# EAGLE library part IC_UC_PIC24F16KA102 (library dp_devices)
16-Bit Flash PIC Microcontroller Mfr no: PIC24F16KA102 PIC24F16KA102
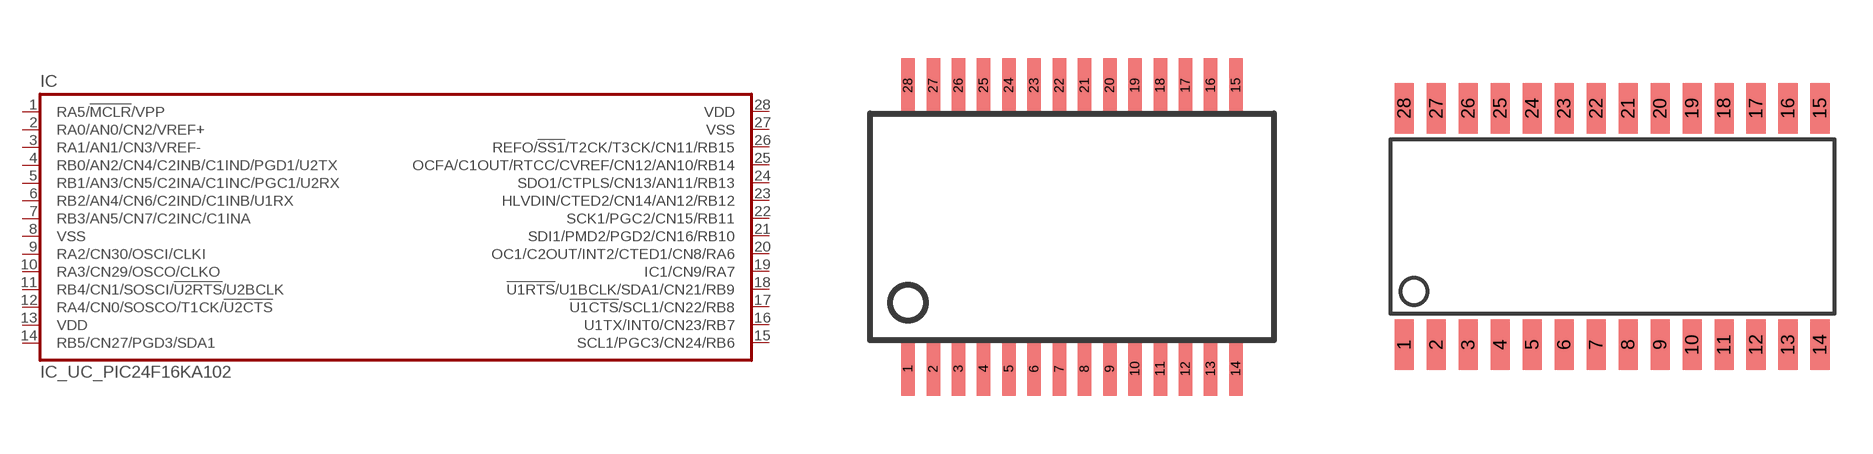
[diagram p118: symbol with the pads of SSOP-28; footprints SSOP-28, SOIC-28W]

Designator prefix IC

## IC_UC_PIC24F16KA102-SSOP  [SSOP-28]
1  RA5/!MCLR!/VPP  in
2  RA0/AN0/CN2/VREF+
3  RA1/AN1/CN3/VREF-
4  RB0/AN2/CN4/C2INB/C1IND/PGD1/U2TX
5  RB1/AN3/CN5/C2INA/C1INC/PGC1/U2RX
6  RB2/AN4/CN6/C2IND/C1INB/U1RX
7  RB3/AN5/CN7/C2INC/C1INA
8  VSS  sup
9  RA2/CN30/OSCI/CLKI
10  RA3/CN29/OSCO/CLKO
11  RB4/CN1/SOSCI/!U2RTS!/U2BCLK
12  RA4/CN0/SOSCO/T1CK/!U2CTS!
13  VDD  sup
14  RB5/CN27/PGD3/SDA1
15  SCL1/PGC3/CN24/RB6
16  U1TX/INT0/CN23/RB7
17  !U1CTS!/SCL1/CN22/RB8
18  !U1RTS!/U1BCLK/SDA1/CN21/RB9
19  IC1/CN9/RA7  pwr
20  OC1/C2OUT/INT2/CTED1/CN8/RA6  pwr
21  SDI1/PMD2/PGD2/CN16/RB10
22  SCK1/PGC2/CN15/RB11
23  HLVDIN/CTED2/CN14/AN12/RB12
24  SDO1/CTPLS/CN13/AN11/RB13
25  OCFA/C1OUT/RTCC/CVREF/CN12/AN10/RB14
26  REFO/!SS1!/T2CK/T3CK/CN11/RB15
27  VSS  sup
28  VDD  sup

## IC_UC_PIC24F16KA102-SOIC  [SOIC-28W]
Pads as for SSOP-28

## Footprint SSOP-28 (pad centres in mm)
SSOP28
smd 0.348 x 1.397: 1 -4.225,-3.656; 2 -3.575,-3.656; 3 -2.925,-3.656; 4 -2.275,-3.656; 5 -1.625,-3.656; 6 -0.975,-3.656; 7 -0.325,-3.656; 8 0.325,-3.656; 9 0.975,-3.656; 10 1.625,-3.656; 11 2.275,-3.656; 12 2.925,-3.656; 13 3.575,-3.656; 14 4.225,-3.656; 15 4.225,3.656; 16 3.575,3.656; 17 2.925,3.656; 18 2.275,3.656; 19 1.625,3.656; 20 0.975,3.656; 21 0.325,3.656; 22 -0.325,3.656; 23 -0.975,3.656; 24 -1.625,3.656; 25 -2.275,3.656; 26 -2.925,3.656; 27 -3.575,3.656; 28 -4.225,3.656

## Footprint SOIC-28W (pad centres in mm)
smd 0.762 x 2: 1 -8.89,-4.7; 2 -7.62,-4.7; 3 -6.35,-4.7; 4 -5.08,-4.7; 5 -3.81,-4.7; 6 -2.54,-4.7; 7 -1.27,-4.7; 8 0,-4.7; 9 1.27,-4.7; 10 2.54,-4.7; 11 3.81,-4.7; 12 5.08,-4.7; 13 6.35,-4.7; 14 7.62,-4.7; 15 7.62,4.7; 16 6.35,4.7; 17 5.08,4.7; 18 3.81,4.7; 19 2.54,4.7; 20 1.27,4.7; 21 0,4.7; 22 -1.27,4.7; 23 -2.54,4.7; 24 -3.81,4.7; 25 -5.08,4.7; 26 -6.35,4.7; 27 -7.62,4.7; 28 -8.89,4.7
